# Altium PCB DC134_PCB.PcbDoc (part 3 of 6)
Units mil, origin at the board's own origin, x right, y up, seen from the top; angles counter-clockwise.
Board outline 4000 x 2750 mil, 6 copper layers (L1_Top Layer, L2_GND1, L3_Signal, L4_Plane, L5_GND2, L6_Bottom Layer), stack 57.7 mil thick; 399 components, 238 nets, 1523 pads, 671 vias.
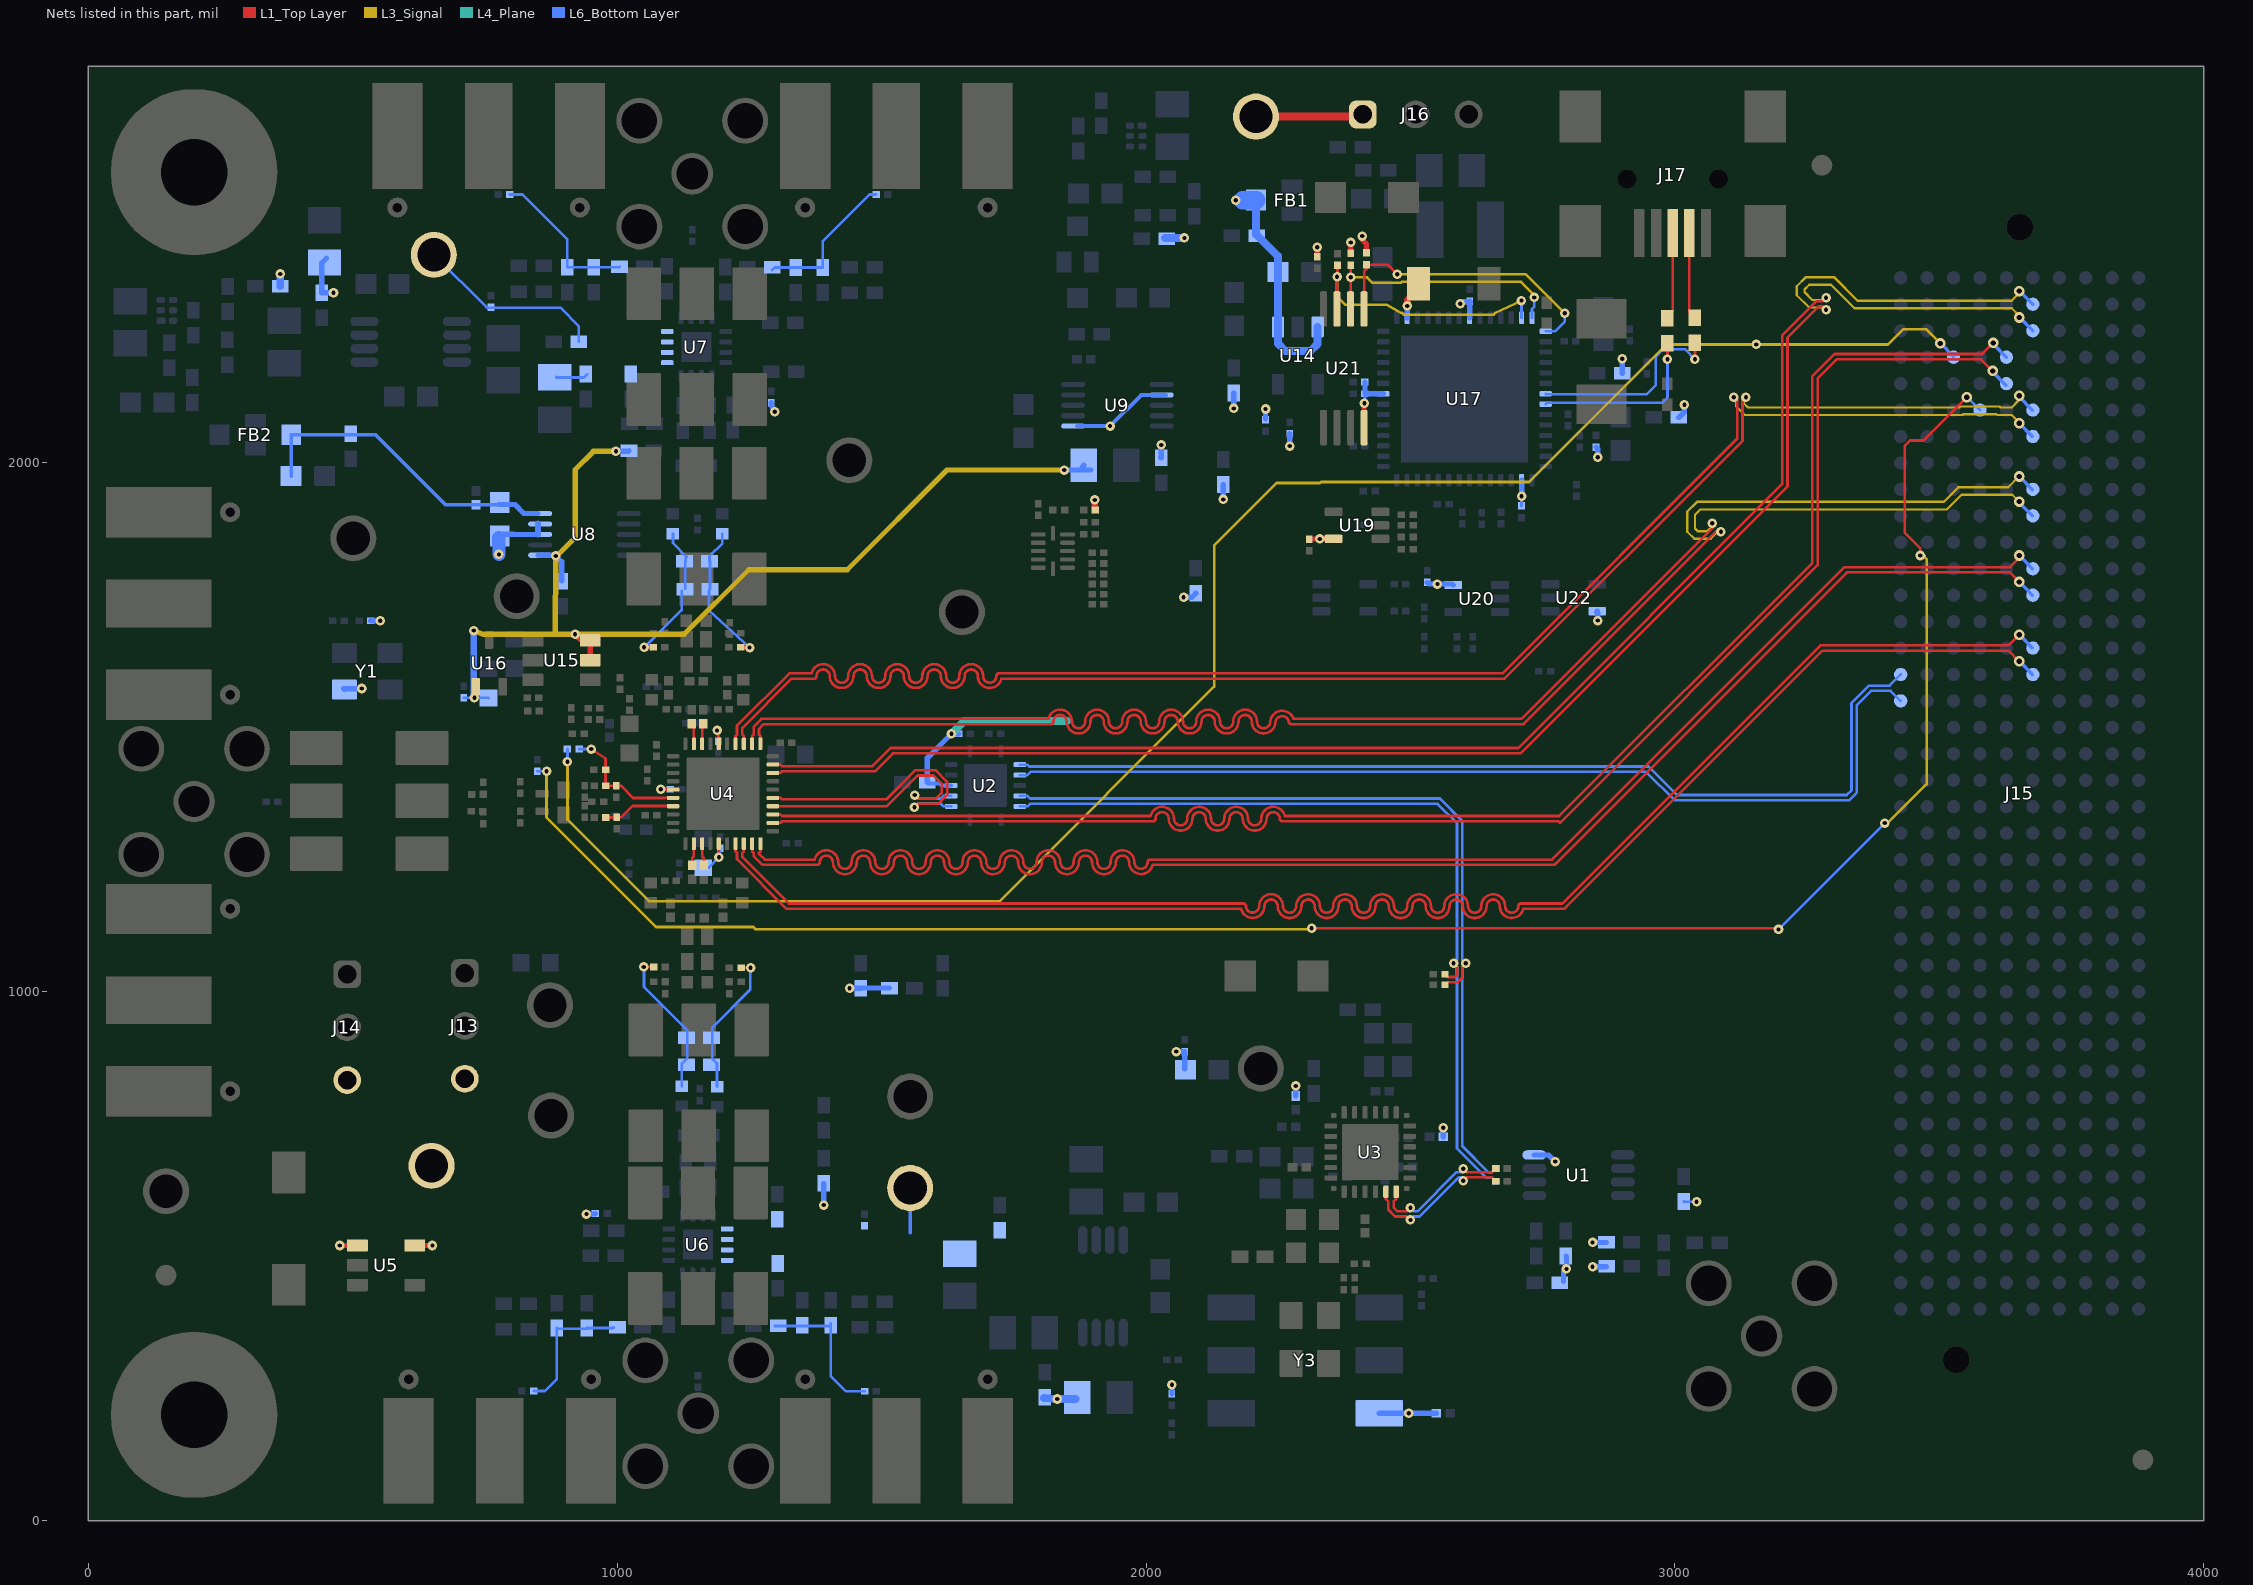
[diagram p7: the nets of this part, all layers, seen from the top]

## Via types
v1: diameter 18, hole 8, L1_Top Layer to L6_Bottom Layer, tented both sides, 429 vias
v2: diameter 20, hole 10, L1_Top Layer to L6_Bottom Layer, tented both sides, 183 vias
v3: diameter 19.68, hole 7.87, L1_Top Layer to L6_Bottom Layer, tented both sides, 37 vias
v4: diameter 19.68, hole 7.87, L1_Top Layer to L6_Bottom Layer, 17 vias
v5: diameter 18, hole 8, L1_Top Layer to L6_Bottom Layer, 5 vias

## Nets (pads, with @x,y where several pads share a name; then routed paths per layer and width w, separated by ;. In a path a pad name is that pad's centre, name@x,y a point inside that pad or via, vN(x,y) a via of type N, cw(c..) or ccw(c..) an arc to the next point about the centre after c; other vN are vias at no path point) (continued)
+3.3V: C18.2 C19.2 C20.2 C22.2 C30.1 C68.1 C75.1 C92.1 C93.2 C100.1 C102.1 C104.1 C106.1 C107.1 C109.1 C110.2 C111.2 C112.2 C125.2 C126.1 C127.1 C128.1 L19.2 L20.1 L21.1 R34.2 R40.2 R50.2 R54.2 R56.1 R64.2 R70.2 R83.2 R91.2 R100.2 R106.2 R125.1 R126.1 R150.1 R153.1 R154.2 R155.2 R158.2 R159.2 R160.2 U1.8 U2.4 U8.6 U9.2 U9.6 U15.5 U15.6 U16.1 U17.16 U17.36 U17.44 U17.50 U19.5 U20.5 U21.8 U22.5 Y3.6 | length 4007.3
  L1_Top Layer w5: v1@2412.39,2112.39 v1(2413,2113)
  L1_Top Layer w10: v1(920.5,1676) 930.1,1666.4 949.13,1666.4 U15.6@949.13,1664.4 U15.5@949.13,1629 ; C126.1@2310.39,1856.02 v1@2328,1856.02 ; R160.2@2324,2390.02 v1(2324,2408) ; v1(2328.39,1856.41) U19.5@2354.71,1856.41 U19.5@2356.5,1856.41 ; R159.2@2387,2398.02 v1(2387,2417) ; v1(2409,2429) 2409,2422 2417,2414 R158.2@2417,2397.02 ; U21.8@2412.39,2066.8 v1@2412.39,2112.39
  L1_Top Layer w12: R150.1@1903,1910.98 v1(1903,1930) ; v1(2494,2297) 2494,2308 2515.07,2329.07 C109.1@2515.07,2339
  L3_Signal w10: v1(729,1683) 747,1676 883,1676 ; v1(997.62,2022) 955,2022 920.75,1987.75 920.75,1858.96 885.87,1824.08 v1(884,1824.08) 883,1676 ; v1(1845.5,1986.5) 1623.5,1986.5 1435,1798 1248.74,1798 1126.74,1676 v1(920.5,1676) 883,1676
  L4_Plane w15: v1(1632.19,1488) 1656.19,1512 1851,1512
  L6_Bottom Layer w5: C104.1@709.78,1555.98 v1(730,1555.98) 756.25,1555.98 C106.1@756.78,1555.44 ; v1@882.37,1825.71 v1(884,1824.08) ; v1(2413,2113) 2414.02,2114.02 C112.2@2414.02,2131 ; C111.2@2710,1918.61 2710,1936.71 v1(2710.29,1937) ; C22.2@3017,603.53 v1(3041,603)
  L6_Bottom Layer w8: C18.2@1586.62,1396 1588.62,1394 1610,1394 1613.96,1390.04 U2.4@1631.51,1390.04 ; U9.6@1869.84,2069.63 v1(1932.13,2069.63) 1991.19,2128.68 U9.2@2037.16,2128.68
  L6_Bottom Layer w10: C102.1@450.5,2387 441.5,2378 R126.1@441.5,2321.62 v1(463.62,2321.62) ; U8.6@850.34,1825.71 v1@882.37,1825.71 ; v1(884,1824.08) 895,1813.08 C75.1@895,1776.62 ; v1(941.87,579.74) 957.85,579.74 R91.2@958.85,580.74 ; v1(997.62,2022) 1021.28,2022 R100.2@1022.28,2023 ; R106.2@1291.38,2113.98 1291.38,2108.6 1298,2098.35 v1(1298,2097) ; v1(1390.87,596.74) R83.2@1390.87,637.12 ; C18.2@1586.62,1396 1586.62,1442.43 v1(1632.19,1488) R50.2@1645.98,1488 ; v1(1845.5,1986.5) C92.1@1896.09,1986.5 ; C92.1@1879.5,1992.5 C92.1@1882.5,1995.5 ; C68.1@2027.61,2010.62 2028.61,2009.62 v1(2029,2034) ; R64.2@2049,240.02 v1(2049,257) ; v1(2057,886.98) C107.1@2073,886.98 R56.1@2073,854.13 ; v1(2071,1746) 2086.62,1746 R154.2@2094,1753.38 ; v1(2146,1931) R155.2@2146,1959.38 ; v1(2166,2103) L19.2@2166,2132.38 ; C128.1@2226,2083.11 v1(2226,2102) ; v1(2272,2032) 2272,2054.89 C93.2@2272.09,2054.98 ; R54.2@2283,802.99 v1(2283,822) ; C125.2@2414.02,2153.12 C112.2@2414.02,2131 2448.32,2131 U17.36@2448.47,2130.84 ; Y3.6@2440.96,203 v1(2497,203) C30.1@2549.01,203 ; U17.44@2493.75,2274.54 2494,2274.79 v1(2494,2297) ; C127.1@2532,1773.98 2534.98,1771 v1(2551,1771) 2579.03,1771 U20.5@2580.82,1769.21 ; R70.2@2561.99,726 v1(2561.99,743.01) ; v1@2596,2305 C110.2@2612,2305 ; U17.50@2611.86,2274.54 2612,2274.68 C110.2@2612,2305 ; v1(2710.29,1937) U17.16@2710.29,1967.46 ; U1.8@2734.34,691.54 2761.44,691.54 v1(2774,678.98) ; C19.2@2789.62,452 2789.62,470.62 v1(2795,476) 2795,499.38 R40.2@2794,500.38 ; v1(2844.38,480.02) C20.2@2870.76,480.02 ; v1(2844.38,526) R34.2@2870.76,526 ; R153.1@2851,2029.98 2854,2026.98 v1(2854,2010.62) ; U22.5@2853.29,1719.41 2852,1718.12 2854,1716.12 v1(2854,1702) ; L21.1@2900.62,2169.5 v1(2900.62,2197) ; L20.1@3007.62,2086 3018,2096.38 v1(3018,2110) ; C110.2@2612,2305 2612.98,2305 C110.2@2612,2305.98 C110.2@2612,2305
  L6_Bottom Layer w12: v1(729,1683) 729.05,1556.93 v1(730,1555.98)
  L6_Bottom Layer w15: R125.1@1807.22,231.62 v1(1832,230) C100.1@1867,230
  other v1: 2594,2301
+5V: C74.1 C90.1 FB1.3 R115.1 R117.1 U14.1 U14.3 | length 501.5
  L6_Bottom Layer w15: R115.1@363,2334.69 v1(363,2357.5) ; R117.1@2036.28,2425.41 v1(2072.61,2425.41) ; v1(2169.83,2496.88) 2177.5,2504.54 ; FB1.3@2208.09,2497 2208.09,2432.33 2249.5,2390.91 C90.1@2249.5,2361 2249.5,2257.23 U14.1@2249.6,2257.13 2249.6,2225.9 2263.5,2212 2311.5,2212 2324.4,2224.9 U14.3@2324.4,2257.13
  L6_Bottom Layer w35: 2183,2497 FB1.3@2208.09,2497
+5V_EXT: +1.1 J16.1 | length 203.7
  L1_Top Layer w15: +1.1@2208,2655 2406,2655 J16.1@2410,2659
-0.23V_CHA: C60.1 C61.1 C95.1 R93.2 R123.2 TP10.1 U6.13 U6.14 U6.15 U6.16 | length 84
  L6_Bottom Layer w7: 1554,545 TP10.1@1554,629
-0.23V_CHB: C62.1 C63.1 C97.1 R110.2 R124.2 TP12.1 U7.13 U7.14 U7.15 U7.16 | length 422.5
  L6_Bottom Layer w5: TP12.1@653.5,2393.5 753.5,2293.5 860.3,2293.5 892.5,2293.5 927.62,2258.38 R124.2@927.62,2229 ; C97.1@885.5,2162.5 884.5,2161.5 937.17,2161.5 C62.1@943.5,2167.83
AIN_N: R5.2 U4.13 | length 38.8
  L1_Top Layer w5: U4.13@1160.75,1279.54 1160.75,1255.63 1163.85,1252.53 R5.2@1163.85,1242.02
AIN_P: R12.2 U4.12 | length 38.8
  L1_Top Layer w5: R12.2@1141.35,1242.02 1141.9,1252.53 1145,1255.63 U4.12@1145,1279.54
AMP_CHA_IN_N: R13.1 R86.1 R89.2 R90.2 | length 257.6
  L6_Bottom Layer w5: R13.1@842.02,245 863.5,245.05 885.87,267.42 R89.2@885.87,364.12 ; R89.2@888.32,363.12 944.32,363.12 R90.2@944.03,362.77 ; R90.2@942.37,364.12 992.25,364.12 R86.1@993.25,365.12
AMP_CHA_IN_P: R2.1 R80.1 R81.1 R84.1 | length 281.9
  L6_Bottom Layer w5: R84.1@1297.86,368.17 R80.1@1403.75,368.17 ; R80.1@1403.75,373.17 R80.1@1403.75,369.62 R80.1@1403.75,368.17 ; R2.1@1468.2,244.5 1432.88,244.5 1403.75,273.63 R80.1@1403.75,368.17
AMP_CHA_OUT_N: C53.2 L12.2 R14.1 R85.1 | length 277.1
  L1_Top Layer w5: v1(1050.5,1047) R14.1@1069.05,1047
  L6_Bottom Layer w5: v1@1050.87,1041.74 1050.87,1009.12 1132.25,927.74 1132.25,874.12 1121.82,863.7 1121.82,822 L12.2@1122.38,821.44
AMP_CHA_OUT_P: C53.1 L11.2 R1.1 R85.2 | length 273.3
  L1_Top Layer w5: R1.1@1234.26,1045.5 v1(1252.24,1045.5)
  L6_Bottom Layer w5: L11.2@1189.43,820.44 1188.87,821 1188.87,864.74 1179.49,874.12 1179.49,931.74 1251.61,1003.86 v1@1251.61,1041.74
AMP_CHB_IN_N: R27.1 R103.1 R107.2 R108.2 | length 284.3
  L6_Bottom Layer w5: R103.1@1293,2364.5 1298.12,2369.62 R108.2@1337.5,2369.62 R107.2@1388.5,2369.62 1388.5,2418.5 1477.5,2507.5 R27.1@1489.48,2507.5
AMP_CHB_IN_P: R16.1 R97.1 R98.1 R101.1 | length 295.8
  L6_Bottom Layer w5: R16.1@796.77,2507.5 821,2507.5 905.5,2423 R98.1@905.5,2370.12 R97.1@955.8,2370.12 1003.5,2370.12 R101.1@1004.38,2371
AMP_CHB_OUT_N: C58.2 L14.2 R28.1 R102.1 | length 274.2
  L1_Top Layer w5: R28.1@1233.42,1651.5 1233.92,1651 v1(1250.5,1651)
  L6_Bottom Layer w5: R102.1@1174.69,1759.07 1173.62,1758 1173.5,1721 v1(1250.5,1651) ; C58.2@1174.69,1814 1174.69,1823.69 1199.04,1848.04 L14.2@1199.04,1866.3 ; R102.1@1175.69,1762.07 C58.2@1175.69,1814
AMP_CHB_OUT_P: C58.1 L13.2 R15.1 R102.2 | length 268.2
  L1_Top Layer w5: v1(1051,1651.5) R15.1@1068.04,1651.5
  L6_Bottom Layer w5: v1@1051.5,1651.5 1121.88,1721.88 R102.2@1121.88,1758.5 ; L13.2@1105.47,1866.3 1105.47,1848.53 C58.1@1131.45,1822.55 ; R102.2@1128.45,1762.07 C58.1@1128.45,1814 ; C58.1@1129.45,1814 C58.1@1129.45,1822.55
AVDD: C40.1 C41.1 C42.1 C43.1 C69.1 J13.3 J14.3 L16.1 R31.2 R112.1 TP6.1 U4.5 U4.15 U4.36 U5.1 U5.5 U8.8 U8.9 Y1.4 | length 498.2
  L1_Top Layer w5: v1(1189,1494.09) U4.36@1192.13,1469.49 ; U4.15@1192.24,1280.06 1192.24,1263 1193,1262.24 v1@1193,1255
  L1_Top Layer w7: v1(1082.5,1383) U4.5@1105.63,1382.42
  L1_Top Layer w10: v1(475.25,520.25) U5.1@508.87,520.25 ; U5.5@617.13,520.25 v1(650.75,520.25) ; v1(1189,1494.09) v1@1190.32,1492.78
  L6_Bottom Layer w5: C43.1@1163,1234.44 1172.44,1234.44 v1(1192.56,1254.56) C41.1@1195,1270.98 ; C42.1@1191,1474.02 v1@1191,1492.09 ; C41.1@1192.56,1270.54 C41.1@1193,1270.98 ; C69.1@1460.5,1006.88 C69.1@1460.62,1007
  L6_Bottom Layer w7.5: v1(1082.5,1383) C40.1@1099.98,1383
  L6_Bottom Layer w10: Y1.4@484.19,1571.55 482.74,1573 v1@520.99,1573 ; R31.2@534,1701.52 v1(551.93,1701.45) ; R112.1@776,1858.58 782.5,1865.08 804.1,1865.08 804.42,1864.76 850.02,1864.76 U8.8@850.34,1865.08 ; v1(1189,1494.09) v1@1191,1492.09 ; v5(1439.38,1006.88) C69.1@1460.5,1006.88 ; C69.1@1460.62,1007 L16.1@1514.88,1007
  L6_Bottom Layer w12: U8.8@850.34,1865.08 U8.9@850.34,1884.76
  L6_Bottom Layer w25: R112.1@776,1858.58 v1(776.5,1827)
  other v1: 517,1573.5
AVDD+: C80.1 C81.1 C82.1 FB2.3 R112.2 U8.10 | length 606.7
  L6_Bottom Layer w7: C80.1@383.5,1975.5 383.5,2052.99 FB2.3@383.91,2053.4 455.91,2053.4 456,2053.5 542.92,2053.5 675.41,1921 775.43,1921 R112.2@776,1921.57
  L6_Bottom Layer w10: R112.2@776,1921.57 806.5,1921.57 823.39,1904.69 U8.10@850.34,1904.45
BIN_N: R26.2 U4.38 | length 38.2
  L1_Top Layer w5: U4.38@1160.75,1474.09 1160.75,1498 1163.85,1501.1 R26.2@1165,1510.98
BIN_P: R19.2 U4.39 | length 38.4
  L1_Top Layer w5: R19.2@1139.98,1510.98 1141.9,1501.1 1145,1498 U4.39@1145,1474.09
CLK_N: C26.2 R52.2 U4.7 | length 136.1
  L1_Top Layer w5: C26.2@978.46,1329.63 988.05,1329.63 988.65,1330.22 R52.2@999,1330.22 1007.8,1330.22 1028.95,1351.38 U4.7@1105.51,1351.38
CLK_P: C21.2 R30.2 R39.2 R44.2 U4.6 | length 246.7
  L1_Top Layer w5: v1(951,1459) 978.02,1441 R30.2@978.02,1420 C21.2@978.02,1390.11 ; C21.2@978.46,1389.67 R44.2@998.44,1389.67 1007.24,1389.67 1030.41,1366.5 1089.33,1366.5 1089.96,1367.13 U4.6@1105.51,1367.13
  L1_Top Layer w12: v1(951,1459) v1@953.87,1459 ; C21.2@978.02,1390.11 C21.2@978.46,1389.67
  L6_Bottom Layer w5: R39.2@928.02,1459 v1(951,1459)
DA0_N: J15.E13 U4.19 | length 3053.9
  L1_Top Layer w5: U4.19@1255.24,1280.06 1255.24,1265.74 1258.11,1262.87 1258.11,1256.86 1274.97,1240 1378,1240 ccw(c1378,1245) 1383,1245 cw(c1395.5,1245) 1408,1245 ccw(c1430.5,1245) 1453,1245 cw(c1465.5,1245) 1478,1245 ccw(c1500.5,1245) 1523,1245 cw(c1535.5,1245) 1548,1245 ccw(c1570.5,1245) 1593,1245 cw(c1605.5,1245) 1618,1245 ccw(c1640.5,1245) 1663,1245 cw(c1675.5,1245) 1688,1245 ccw(c1710.5,1245) 1733,1245 cw(c1745.5,1245) 1758,1245 ccw(c1780.5,1245) 1803,1245 cw(c1815.5,1245) 1828,1245 ccw(c1850.5,1245) 1873,1245 cw(c1885.5,1245) 1898,1245 ccw(c1920.5,1245) 1943,1245 cw(c1955.5,1245) 1968,1245 ccw(c1990.5,1245) 2012.44,1240 2772.14,1240 2775.07,1242.93 3325.14,1793 3634,1793 3651,1776 v2(3651,1775)
  L6_Bottom Layer w6.6: v2@3652,1775 J15.E13@3676,1750.15
DA0_P: J15.E12 U4.20 | length 3041.3
  L1_Top Layer w5: U4.20@1270.98,1280.06 1270.98,1265.74 1268.11,1262.87 1268.11,1261 1279.11,1250 1373.56,1250 cw(c1395.5,1245) 1418,1245 ccw(c1430.5,1245) 1443,1245 cw(c1465.5,1245) 1488,1245 ccw(c1500.5,1245) 1513,1245 cw(c1535.5,1245) 1558,1245 ccw(c1570.5,1245) 1583,1245 cw(c1605.5,1245) 1628,1245 ccw(c1640.5,1245) 1653,1245 cw(c1675.5,1245) 1698,1245 ccw(c1710.5,1245) 1723,1245 cw(c1745.5,1245) 1768,1245 ccw(c1780.5,1245) 1793,1245 cw(c1815.5,1245) 1838,1245 ccw(c1850.5,1245) 1863,1245 cw(c1885.5,1245) 1908,1245 ccw(c1920.5,1245) 1933,1245 cw(c1955.5,1245) 1978,1245 ccw(c1990.5,1245) 2003,1245 cw(c2008,1245) 2008,1250 2768,1250 3321,1803 3634,1803 3651,1820 v2(3651,1825)
  L6_Bottom Layer w6.6: v2@3652,1825 J15.E12@3676,1800.15
DA1_N: J15.E16 U4.17 | length 3034.6
  L1_Top Layer w5: U4.17@1223.74,1280.06 1223.74,1265.74 1226.61,1262.87 1226.61,1250.86 1320.47,1157 2179.64,1157 ccw(c2201.5,1162.32) 2224,1161.91 ; 2224,1162 cw(c2236.5,1162) 2249,1162 ccw(c2271.5,1162) 2294,1162 cw(c2306.5,1162) 2319,1162 ccw(c2341.5,1162) 2364,1162 cw(c2376.5,1162) 2389,1162 ccw(c2411.5,1162) 2434,1162 cw(c2446.5,1162) 2459,1162 ccw(c2481.5,1162) 2504,1162 cw(c2516.5,1162) 2529,1162 ccw(c2551.5,1162) 2574,1162 cw(c2586.5,1162) 2599,1162 ccw(c2621.5,1162) 2644,1162 cw(c2656.5,1162) 2669,1162 ccw(c2691.5,1162) 2713.44,1157 2791.49,1157 2794.42,1159.93 3279.49,1645 3631,1645 3651,1625 v2(3651,1624.78)
  L6_Bottom Layer w6.6: v2@3652,1624.78 J15.E16@3676,1599.92
DA1_P: J15.E15 U4.18 | length 3021.3
  L1_Top Layer w5: U4.18@1239.49,1280.06 1239.49,1265.74 1236.61,1262.87 1236.61,1255 1324.61,1167 2184,1167 cw(c2184,1162) 2189,1162.09 ; 2189,1162 ccw(c2184,1162) 2189,1162.09 ; 2214,1162 cw(c2236.5,1162) 2214,1162.05 ; v2(3651,1675) 3631,1655 3275.35,1655 2787.35,1167 2709,1167 ccw(c2709,1162) 2704,1162 cw(c2691.5,1162) 2679,1162 ccw(c2656.5,1162) 2634,1162 cw(c2621.5,1162) 2609,1162 ccw(c2586.5,1162) 2564,1162 cw(c2551.5,1162) 2539,1162 ccw(c2516.5,1162) 2494,1162 cw(c2481.5,1162) 2469,1162 ccw(c2446.5,1162) 2424,1162 cw(c2411.5,1162) 2399,1162 ccw(c2376.5,1162) 2354,1162 cw(c2341.5,1162) 2329,1162 ccw(c2306.5,1162) 2284,1162 cw(c2271.5,1162) 2259,1162 ccw(c2236.5,1162) 2214,1162.05 ; 2189,1162.09 ccw(c2201.5,1162.32) 2214,1162.05
  L6_Bottom Layer w6.6: v2@3652,1675 J15.E15@3676,1650.15
DB0_N: J15.E10 U4.32 | length 3005.6
  L1_Top Layer w5: U4.32@1255.24,1469.03 1255.24,1483.34 1258.11,1486.22 1258.11,1501.14 1272.97,1516 1815.56,1516 cw(c1837.5,1511) 1860,1511 ccw(c1872.5,1511) 1885,1511 cw(c1907.5,1511) 1930,1511 ccw(c1942.5,1511) 1955,1511 cw(c1977.5,1511) 2000,1511 ccw(c2012.5,1511) 2025,1511 cw(c2047.5,1511) 2070,1511 ccw(c2082.5,1511) 2095,1511 cw(c2117.5,1511) 2140,1511 ccw(c2152.5,1511) 2165,1511 cw(c2187.5,1511) 2210,1511 ccw(c2222.5,1511) 2235,1511 ; 2235.04,1511.65 cw(c2257.5,1508.72) 2278.95,1516 2710,1516 3074,1880 3074,1883 v1(3070.9,1886.1)
  L3_Signal w4.4: v1(3070.9,1886.1) 3070.9,1880.02 3061.94,1871.06 3042.94,1871.06 3038,1876 3038,1902 3048,1912 3514.29,1912 3542.1,1939.82 3638,1939.82 v2(3651,1927)
  L6_Bottom Layer w6.6: v2@3651,1925 J15.E10@3676,1900
DB0_P: J15.E9 U4.31 | length 3062.8
  L1_Top Layer w5: U4.31@1270.98,1469.03 1270.98,1483.34 1268.11,1486.22 1268.11,1497 1277.11,1506 1820,1506 ccw(c1820,1511) 1825,1511 cw(c1837.5,1511) 1850,1511 ccw(c1872.5,1511) 1895,1511 cw(c1907.5,1511) 1920,1511 ccw(c1942.5,1511) 1965,1511 cw(c1977.5,1511) 1990,1511 ccw(c2012.5,1511) 2035,1511 cw(c2047.5,1511) 2060,1511 ccw(c2082.5,1511) 2105,1511 cw(c2117.5,1511) 2130,1511 ccw(c2152.5,1511) 2175,1511 cw(c2187.5,1511) 2200,1511 ccw(c2222.5,1511) 2245,1510.63 cw(c2257.5,1508.72) 2270.04,1510.38 ccw(c2275,1511) 2275,1506 2714.14,1506 3081.07,1872.93 3084.07,1872.93 v1(3087.17,1869.83)
  L3_Signal w4.4: v1(3087.17,1869.83) 3081.09,1869.83 3067.91,1856.66 3036.98,1856.66 3023.6,1870.04 3023.6,1907.96 3042.04,1926.4 3508.32,1926.4 3536.14,1954.22 3630.25,1954.22 3650.45,1974.42 v2(3651,1974.42)
  L6_Bottom Layer w6.6: v2@3652,1974.42 J15.E9@3676,1949.57
DB1_N: J15.E7 U4.34 | length 3038.3
  L1_Top Layer w5: U4.34@1223.74,1469.03 1223.74,1483.34 1226.61,1486.22 1226.61,1503.14 1325.47,1602 1367.56,1602 cw(c1389.5,1597) 1412,1597 ccw(c1424.5,1597) 1437,1597 cw(c1459.5,1597) 1482,1597 ccw(c1494.5,1597) 1507,1597 cw(c1529.5,1597) 1552,1597 ccw(c1564.5,1597) 1577,1597 cw(c1599.5,1597) 1622,1597 ccw(c1634.5,1597) 1647,1597 cw(c1669.5,1597) 1692,1597 ccw(c1704.5,1597) 1717,1597 cw(c1722,1597) 1722,1602 2674,1602 3118,2046 3118,2122 3115.66,2124.34 v1(3111.5,2124.34)
  L3_Signal w4.4: v1(3111.5,2124.34) 3115.8,2120.04 3115.8,2107.04 3132.24,2090.6 3544.02,2090.6 3545.62,2092.2 3608.12,2092.2 3609.72,2090.6 3637,2090.6 3651,2076.6 v2(3651,2075)
  L6_Bottom Layer w6.6: v2(3651,2075) J15.E7@3676,2050
DB1_P: J15.E6 U4.33 | length 3020.9
  L1_Top Layer w5: U4.33@1239.49,1469.03 1239.49,1483.34 1236.61,1486.22 1236.61,1499 1329.61,1592 1372,1592 ccw(c1372,1597) 1377,1597 cw(c1389.5,1597) 1402,1597 ccw(c1424.5,1597) 1447,1597 cw(c1459.5,1597) 1472,1597 ccw(c1494.5,1597) 1517,1597 cw(c1529.5,1597) 1542,1597 ccw(c1564.5,1597) 1587,1597 cw(c1599.5,1597) 1612,1597 ccw(c1634.5,1597) 1657,1597 cw(c1669.5,1597) 1682,1597 ccw(c1704.5,1597) 1726.44,1592 2678.14,1592 3128,2041.86 3128,2122 3130.34,2124.34 v1(3134.5,2124.34)
  L3_Signal w4.4: v1(3134.5,2124.34) 3130.2,2120.04 3130.2,2113 3138.2,2105 3538.05,2105 3539.65,2106.6 3614.09,2106.6 3615.69,2105 3637,2105 3651,2119 v2(3651,2127)
  L6_Bottom Layer w6.6: v2@3651,2125 J15.E6@3676,2100
DCLK_N: J15.F5 U4.22 | length 3063.9
  L1_Top Layer w5: U4.22@1294.49,1319.2 U4.22@1294.49,1319.88 ; U4.22@1294.61,1319.43 1308.92,1319.43 1311.79,1322.3 1659.91,1322.3 1660.11,1322.5 1673.78,1322.5 1673.98,1322.3 2013,1322.3 ccw(c2013,1327.3) 2018,1327.3 cw(c2030.5,1327.3) 2043,1327.3 ccw(c2065.5,1327.3) 2088,1327.3 cw(c2100.5,1327.3) 2113,1327.3 ccw(c2135.5,1327.3) 2158,1327.3 cw(c2170.5,1327.3) 2183,1327.3 ccw(c2205.5,1327.3) 2228,1327.3 cw(c2240.5,1327.3) 2253,1327.3 ccw(c2258,1327.3) 2258,1322.3 2779.69,1322.3 2782.57,1319.43 3270,1806.86 3270,2160 3306,2196 3579,2196 v2(3601,2174)
  L6_Bottom Layer w6.6: v2@3601,2172 J15.F5@3626,2147
DCLK_P: J15.F4 U4.23 | length 3058.2
  L1_Top Layer w5: U4.23@1294.61,1335.17 1308.92,1335.17 1311.79,1332.3 1655.77,1332.3 1655.97,1332.5 1677.92,1332.5 1678.12,1332.3 2008.56,1332.3 cw(c2030.5,1327.3) 2053,1327.3 ccw(c2065.5,1327.3) 2078,1327.3 cw(c2100.5,1327.3) 2123,1327.3 ccw(c2135.5,1327.3) 2148,1327.3 cw(c2170.5,1327.3) 2193,1327.3 ccw(c2205.5,1327.3) 2218,1327.3 cw(c2240.5,1327.3) 2262.44,1332.3 2781.3,1332.3 3260,1811 3260,2164.14 3301.86,2206 3581,2206 v2(3602,2227)
  L6_Bottom Layer w6.6: v2@3602,2225 J15.F4@3627,2200
DCLKIN_CDC_N: R32.2 U3.6 | length 274.7
  L1_Top Layer w5: U3.6@2473.21,622.2 2473.21,607.89 2468.37,603.04 2468.37,592 2475.37,585 2493.5,585 v1(2500,591.5) ; v1(2600,665.5) 2606.5,659 2653.98,659 R32.2@2660.98,666
  L6_Bottom Layer w5: v1(2500,591.5) 2506.5,585 2513,585 2587,659 2598,659 2600,661 v1(2600,665.5)
DCLKIN_CDC_P: R38.2 U3.5 | length 291.2
  L1_Top Layer w5: U3.5@2453.53,622.2 2453.53,607.89 2458.37,603.04 2458.37,587.86 2471.23,575 2493.5,575 v1(2500,568.5) ; v1(2600,642.5) 2606.5,649 2653.98,649 R38.2@2660.98,642
  L6_Bottom Layer w5: v1(2500,568.5) 2506.5,575 2517.14,575 2591.14,649 2598,649 2600,647 v1(2600,642.5)
DCLKIN_FPGA_N: J15.K16 U2.9 | length 1880.5
  L6_Bottom Layer w5: U2.9@1761.44,1429.41 1775.75,1429.41 1779.16,1426 2950,1426 3003.99,1372.01 3325.01,1372.01 3334,1381 3334,1546.14 3363.93,1576.07 3366.86,1579 3406,1579 J15.K16@3427,1600
DCLKIN_FPGA_P: J15.K17 U2.10 | length 1881
  L6_Bottom Layer w5: U2.10@1761.44,1409.73 1775.75,1409.73 1782.02,1416 2945.86,1416 2999.84,1362.01 ; 2999.93,1361.93 2999.84,1362.01 ; J15.K17@3427,1550 3408,1569 3371,1569 3344,1542 3344,1376.86 3329.16,1362.01 2999.84,1362.01
DCLKIN_N: U2.3 U4.24 | length 498.5
  L1_Top Layer w5: U4.24@1294.61,1350.92 1509.92,1350.92 1568,1409 1598,1409 1614,1393 1614,1376.51 1603,1365.51 1569.25,1365.51 v1(1562.75,1372.01)
  L6_Bottom Layer w5: v1(1562.75,1372.01) 1569.25,1365.51 1612.36,1365.51 1617.2,1370.36 U2.3@1631.51,1370.36
DCLKIN_P: U2.2 U4.25 | length 532.9
  L1_Top Layer w5: U4.25@1294.61,1366.67 1308.92,1366.67 1311.52,1364.07 1508.93,1364.07 1563.86,1419 1602.14,1419 1624,1397.14 1624,1372.37 1607.14,1355.51 1568.5,1355.51 v1(1562,1349.01)
  L6_Bottom Layer w5: v1(1562,1349.01) 1568.5,1355.51 1612.36,1355.51 1617.2,1350.67 U2.2@1631.51,1350.67
DCLKIN_SMA_N: R35.2 R62.2 U2.12 | length 1630.9
  L1_Top Layer w5: R62.2@2565.38,1013.02 2570.35,1018 2589.14,1018 2598,1026.86 2598,1047.5 v1(2604.5,1054)
  L6_Bottom Layer w5: U2.12@1761.44,1370.36 1775.75,1370.36 1780.59,1365.51 2555.49,1365.51 2598,1323 2598,1060.5 v1(2604.5,1054) 2598,1047.5 2598,708 2647,659 2653.98,659 R35.2@2660.98,666
DCLKIN_SMA_P: R36.2 R60.2 U2.13 | length 1614.4
  L1_Top Layer w5: R60.2@2565.38,1033.02 2570.4,1028 2585,1028 2588,1031 2588,1047.5 v1(2581.5,1054)
  L6_Bottom Layer w5: U2.13@1761.44,1350.67 1775.75,1350.67 1780.59,1355.51 2551.34,1355.51 2588,1318.86 2588,1060.5 v1(2581.5,1054) 2588,1047.5 2588,703.86 2642.86,649 2653.98,649 R36.2@2660.98,642
DM-CON: J17.2 R145.1 | length 143.5
  L1_Top Layer w5: J17.2@3027.5,2416.64 3027.5,2285.13 R145.1@3036,2276.62
DM-FTDI: R145.2 U17.7 | length 388.9
  L1_Top Layer w5: v1(3038,2196) R145.2@3038,2227.38
  L6_Bottom Layer w5: U17.7@2755.56,2130.84 2756.4,2130 2947,2130 2964,2147 2964,2201 2978,2215 3019,2215 v1(3038,2196)
DP-CON: J17.3 R148.1 | length 146
  L1_Top Layer w5: R148.1@2984,2275.62 2996,2287.62 J17.3@2996,2416.64
DP-FTDI: R148.2 U17.8 | length 338.3
  L1_Top Layer w5: v1(2986,2196) R148.2@2986,2226.38
  L6_Bottom Layer w5: U17.8@2755.56,2111.16 2758.08,2113.68 2976,2113.68 2986,2123.68 v1(2986,2196)
EECLK: R159.1 U17.56 U21.2 | length 490.3
  L1_Top Layer w5: U21.2@2386.8,2291.2 2387,2291.41 v1(2387,2351) R159.1@2387,2374
  L3_Signal w5: v1(2387,2351) 2418,2351 2428.5,2340.5 2481.83,2340.5 2483.83,2342.5 2709.5,2342.5 2734,2318 v1(2734,2313)
  L6_Bottom Layer w5: U17.56@2729.97,2274.54 2729.97,2291 2734,2295.03 v1(2734,2313)
EECS: R158.1 U17.1 U21.1 | length 558.5
  L1_Top Layer w5: U21.1@2412.39,2291.2 2412.39,2362 2417,2366.61 R158.1@2417,2374.98 2457.02,2374.98 v1(2475,2357)
  L3_Signal w5: v1(2475,2357) 2718,2357 v1(2792,2283)
  L6_Bottom Layer w5: U17.1@2755.56,2248.95 2773.62,2248.95 2792,2267.33 v1(2792,2283)
EEDATA: R162.2 U17.55 U21.3 | length 520.3
  L1_Top Layer w5: U21.3@2361.2,2291.2 v1(2361.2,2352.2) 2362,2353 R162.2@2362,2373.98
  L3_Signal w5: v1(2361.2,2352.2) 2361.2,2314.8 2377,2299 2455,2299 2481.83,2284 2483.67,2284 2487.17,2280.5 2657.33,2280.5 2660.83,2284 v1(2710,2307)
  L6_Bottom Layer w5: v1(2710,2307) 2710,2274.83 U17.55@2710.29,2274.54
FCLK_N: J15.E3 U4.29 | length 3051
  L1_Top Layer w5: U4.29@1294.61,1429.66 1308.92,1429.66 1311.79,1426.79 1483,1426.79 1517.21,1461 2704,1461 3203,1960 3203,2241.14 3267.86,2306 3279.5,2306 v1(3286,2312.5)
  L3_Signal w4.4: v1(3286,2312.5) 3281.7,2308.2 3260,2308.2 3245,2323.2 3245,2328 3254,2337 3295,2337 3339.6,2292.4 3416.09,2292.4 3416.29,2292.6 3637,2292.6 3651,2278.6 v2(3651,2275)
  L6_Bottom Layer w6.6: v2@3652,2275 J15.E3@3677,2250
FCLK_P: J15.E2 U4.28 | length 3099.1
  L1_Top Layer w5: U4.28@1294.61,1413.91 1308.92,1413.91 1311.79,1416.79 1487.14,1416.79 1521.35,1451 2708.14,1451 3213,1955.86 3213,2237 3272,2296 3279.5,2296 v1(3286,2289.5)
  L3_Signal w4.4: v1(3286,2289.5) 3281.7,2293.8 3254.04,2293.8 3230.6,2317.24 3230.6,2333.96 3248.04,2351.4 3300.96,2351.4 3345.56,2306.8 3410.12,2306.8 3410.32,2307 3637,2307 3651,2321 v2(3651,2325)
  L6_Bottom Layer w6.6: v2@3652,2325 J15.E2@3677,2300
FPGA_CLK: J15.H4 R39.1 | length 3445.2
  L3_Signal w5: v1(906,1435) 906,1325.5 1060,1171.5 1723.5,1171.5 2129,1577 2129,1844 2247,1962 2329,1962 2331,1964 2724,1964 2984,2224 v1(3154,2224) 3403,2224 3432,2253 3475,2253 v2(3502,2226)
  L6_Bottom Layer w5: v1(906,1435) R39.1@905.98,1459 ; v1@3151.83,2224 v1(3154,2224)
  L6_Bottom Layer w6.6: v2@3503,2226 J15.H4@3526.75,2201.41
FPGA_REFCLK: J15.G6 R29.2 | length 3769.2
  L1_Top Layer w5: v1(2313,1120) 3194,1120 v1(3196,1118) ; v1(3464,1825) 3464,1839.25 3434.5,1868.75 3434.5,2032.25 3444.75,2042.5 3470.16,2042.5 v2(3552,2124.34)
  L3_Signal w5: v1(866.53,1416.98) 866.53,1329.85 1073.88,1122.5 1257.57,1122.5 1262.07,1118 2311,1118 v1(2313,1120) ; v1(3397,1319) 3402,1319 3476,1393 3476,1818 3472.08,1821.92 3472.08,1825 v1(3464,1825)
  L6_Bottom Layer w5: R29.2@849.15,1416.98 v1(866.53,1416.98) ; v1(3196,1118) v1(3397,1319) ; v2(3552,2124.34) 3552.66,2124.34 J15.G6@3577,2100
